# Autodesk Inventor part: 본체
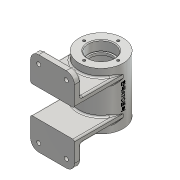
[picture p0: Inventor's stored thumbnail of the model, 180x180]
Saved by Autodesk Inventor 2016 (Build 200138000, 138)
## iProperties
Created: 2017-02
Part Number: 본체
Material: 알루미늄 6061
Document SubType Name: Modeling
Designer: H
Density: 2.7 g/cm^3
Appearance: 알루미늄 - 평지
Mass: 354.768 g
Surface Area: 422.772 cm^2
Volume: 131.396 cm^3
Author: H
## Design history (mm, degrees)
sketch "스케치1"
  geometry: C1 r 27 at (0, 0); 1 further point
  constraints: 1 centre point, 1 coincident
  dimensions: "d0" = 54 diameter of C1
extrude "돌출1" new body sketch "스케치1" stored distance "d1" = 70; taper "d2" = 0 deg
sketch "스케치2"
  geometry: L1 (0, 17)-(-60, 17); L2 (-60, 17)-(-60, 25); L3 (-52, 25)-(0, 25); L4 (0, 25)-(0, 17); L5 (-52, 25)-(-52, 52); L6 (-52, 52)-(-60, 52); L7 (-60, 52)-(-60, 25); 1 further point
  constraints: 14 end point, 3 parallel, 1 horizontal, 1 perpendicular
  dimensions: "d3" = 17 distance from line of L1 point (0, 0); "d5" = 60 distance of L1.start L1.end; "d6" = 60 distance from line of point (0, 0) L2; "d7" = 8 distance of L5.end L6.end; "d8" = 52 distance from line of point (0, 0) L6; "d9" = 8 distance of L3.end L1.start; "d10" = 90 deg angle of L3 L5; "d11" = 27 distance of L3.start L5.end; "d12" = 8 distance of L1.end L2.end
extrude "돌출2" join sketch "스케치2" stored distance "d13" = 54; taper "d14" = 0 deg
sketch "스케치3"
  geometry: C1 r 16 at (0, 0); 1 further point
  constraints: 1 centre point, 1 coincident
  dimensions: "d15" = 32 diameter of C1
extrude "돌출3" cut sketch "스케치3" distance "d16" = 12; taper "d17" = 0 deg
sketch "스케치4"
  geometry: C1 r 16 at (0, 0); 1 further point
  constraints: 1 centre point, 1 coincident
  dimensions: "d18" = 32 diameter of C1
extrude "돌출4" cut sketch "스케치4" distance "d19" = 12; taper "d20" = 0 deg
sketch "스케치5"
  geometry: C1 r 14 at (0, 0); 1 further point
  constraints: 1 centre point, 1 coincident
  dimensions: "d21" = 28 diameter of C1
extrude "돌출5" cut sketch "스케치5" distance "d22" = 3; taper "d23" = 0 deg
sketch "스케치6"
  geometry: C1 r 14 at (0, 0); 1 further point
  constraints: 1 centre point, 1 coincident
  dimensions: "d24" = 28 diameter of C1
extrude "돌출6" cut sketch "스케치6" distance "d25" = 3; taper "d26" = 0 deg
sketch "스케치7"
  geometry: C1 r 22 at (0, 0); 1 further point
  constraints: 1 centre point, 1 coincident
  dimensions: "d27" = 44 diameter of C1
extrude "돌출7" cut sketch "스케치7" stored distance "d28" = 3; taper "d29" = 0 deg
node "작업 평면1"
sketch "스케치8"
  geometry: L1 (54, 18)-(0, 18) reference; L2 (54, 8)-(54, 35) reference; C1 r 5 at (27, -7)
  constraints: 1 centre point
  dimensions: "d31" = 25 distance from line of C1.centre L1; "d32" = 10 diameter of C1; "d33" = 27 distance from line of C1.centre L2
extrude "돌출8" join sketch "스케치8" stored distance "d34" = 3; taper "d35" = 0 deg
sketch "스케치9"
  geometry: 2 further points
hole "구멍1" sketch "스케치9" at (0, 0) diameter "d36" = 5.188; stored, may be unused: countersink angle "d40" = 90 deg, drill point angle "d42" = 118 deg; dims "d37" = 12, "d38" = 4, "d39" = 2, "d41" = 14
sketch "스케치10"
  geometry: L1 (0, 0)-(48.075, 0); 1 further point
  constraints: 2 end point, 1 horizontal, 1 point on line
  dimensions: "d43" = 21 distance of L1.start point (21, 0)
hole "구멍2" sketch "스케치10" at (21, 0) diameter "d44" = 3.242; stored, may be unused: countersink angle "d48" = 90 deg, drill point angle "d50" = 118 deg; dims "d45" = 8, "d46" = 4, "d47" = 2, "d49" = 10
sketch "스케치11"
  geometry: L1 (0, 0)-(41.05, 0); 1 further point
  constraints: 2 end point, 1 horizontal, 1 point on line
  dimensions: "d54" = 21 distance of L1.start point (21, 0)
hole "구멍3" sketch "스케치11" at (21, 0) diameter "d55" = 3.242; stored, may be unused: countersink angle "d59" = 90 deg, drill point angle "d61" = 118 deg; dims "d56" = 8, "d57" = 4, "d58" = 2, "d60" = 10
fillet "모깎기1" dims "d65" = 10
sketch "스케치12" dims "d66" = 9
  geometry: L1 (39.5, -14.402)-(44, -11.804); L2 (44, -11.804)-(48.5, -14.402); L3 (48.5, -14.402)-(48.5, -19.598); L4 (48.5, -19.598)-(44, -22.196); L5 (44, -22.196)-(39.5, -19.598); L6 (39.5, -19.598)-(39.5, -14.402); A1 r 10 centre (44, -17) between (44, -27) and (54, -17) reference; 4 further points
  constraints: 12 end point, 1 coincident, 1 horizontal alignment, 1 midpoint, 16 other
  dimensions: "d67" = 2.59808 vertical distance of L1.end L2.end
extrude "돌출9" cut sketch "스케치12" distance "d68" = 3; taper "d69" = 0 deg
sketch "스케치13"
  geometry: C1 r 2.5 at (44, -17); A1 r 10 centre (44, -17) between (44, -27) and (54, -17) reference; 1 further point
  constraints: 1 centre point, 1 concentric
  dimensions: "d70" = 5 diameter of C1
extrude "돌출10" cut sketch "스케치13" stored distance "d71" = 3; taper "d72" = 0 deg
sketch "스케치14"
  geometry: L1 (0, 0)-(-16.339, -25.16); L2 (0, 0)-(0, -85.016)
  constraints: 4 end point, 1 vertical
  dimensions: "d73" = 33 deg angle of L1 L2; "d74" = 30 distance of L1.start L1.end
node "작업 평면2"
sketch "스케치15"
  geometry: C1 r 6 at (0, 0); 1 further point
  constraints: 1 centre point, 1 coincident
  dimensions: "d75" = 12 diameter of C1
extrude "돌출11" join sketch "스케치15" stored distance "d76" = 3; taper "d77" = 0 deg
sketch "스케치16"
  geometry: 2 further points
  constraints: 1 coincident
hole "구멍4" sketch "스케치16" at (0, 0) diameter "d78" = 5.188; stored, may be unused: countersink angle "d82" = 90 deg, drill point angle "d84" = 118 deg; dims "d79" = 12, "d80" = 4, "d81" = 2, "d83" = 16
node "작업 평면3"
sketch "스케치17"
  geometry: 2 further points
  constraints: 1 coincident, 1 other
feature "엠보싱1" sketch "스케치17" dims "d86" = 0.5, "d87" = 0
fillet "모깎기2" dims "d88" = 3
fillet "모깎기3" dims "d89" = 0.3
chamfer "모따기1" distance "d90" = 1; stored, may be unused: second distance "d91" = 2, angle "d92" = 45 deg
fillet "모깎기4" dims "d93" = 2
fillet "모깎기5" dims "d94" = 2
fillet "모깎기6" dims "d95" = 2
fillet "모깎기7" dims "d96" = 2
fillet "모깎기8" dims "d97" = 2
fillet "모깎기9" dims "d98" = 2
node "솔리드1"
mirror "대칭1"
pattern_circular "원형 패턴1" dims angle "d52" = 360 deg
pattern_circular "원형 패턴2" dims angle "d63" = 360 deg
mirror "대칭2"
mirror "대칭6"
mirror "대칭4"
mirror "대칭5"
other parameters: "d30" = -92
